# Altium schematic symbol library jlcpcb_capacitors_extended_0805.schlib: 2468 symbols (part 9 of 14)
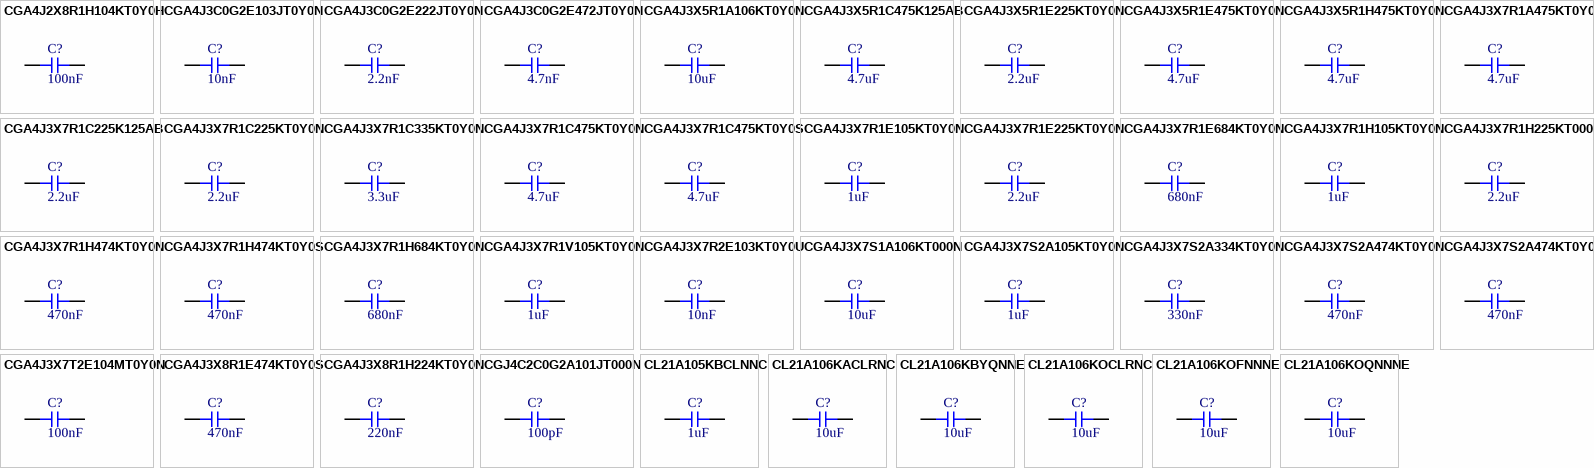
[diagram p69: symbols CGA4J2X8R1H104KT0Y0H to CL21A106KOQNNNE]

## CGA4J3X8R1H224KT0Y0N
designator C?  Capacitance: 220nF  (hidden comment: *)
Capacitor, Ceramic (MLCC), 220nF, ±10%, 50V, X8R, ±10%, SMD 0805; Manufacturer: TDK; Manufacturer Part Number: CGA4J3X8R1H224KT0Y0N
footprint CAP-0805 (0805 (2012M) Capacitor)
pins: 1, 2

## CGJ4C2C0G2A101JT000N
designator C?  Capacitance: 100pF  (hidden comment: *)
Capacitor, Ceramic (MLCC), 100pF, ±5%, 100V, C0G, ±5%, SMD 0805; Manufacturer: TDK; Manufacturer Part Number: CGJ4C2C0G2A101JT000N
footprint CAP-0805 (0805 (2012M) Capacitor)
pins: 1, 2

## CL21A105KBCLNNC
designator C?  Capacitance: 1uF  (hidden comment: *)
Capacitor, Ceramic (MLCC), 1uF, ±10%, 50V, X5R, ±10%, SMD 0805; Manufacturer: Samsung Electro-Mechanics; Manufacturer Part Number: CL21A105KBCLNNC
footprint CAP-0805 (0805 (2012M) Capacitor)
pins: 1, 2

## CL21A106KACLRNC
designator C?  Capacitance: 10uF  (hidden comment: *)
Capacitor, Ceramic (MLCC), 10uF, ±10%, 25V, X5R, ±10%, SMD 0805; Manufacturer: Samsung Electro-Mechanics; Manufacturer Part Number: CL21A106KACLRNC
footprint CAP-0805 (0805 (2012M) Capacitor)
pins: 1, 2

## CL21A106KBYQNNE
designator C?  Capacitance: 10uF  (hidden comment: *)
Capacitor, Ceramic (MLCC), 10uF, ±10%, 50V, X5R, ±10%, SMD 0805; Manufacturer: Samsung Electro-Mechanics; Manufacturer Part Number: CL21A106KBYQNNE
footprint CAP-0805 (0805 (2012M) Capacitor)
pins: 1, 2

## CL21A106KOCLRNC
designator C?  Capacitance: 10uF  (hidden comment: *)
Capacitor, Ceramic (MLCC), 10uF, ±10%, 16V, X5R, ±10%, SMD 0805; Manufacturer: Samsung Electro-Mechanics; Manufacturer Part Number: CL21A106KOCLRNC
footprint CAP-0805 (0805 (2012M) Capacitor)
pins: 1, 2

## CL21A106KOFNNNE
designator C?  Capacitance: 10uF  (hidden comment: *)
Capacitor, Ceramic (MLCC), 10uF, ±10%, 16V, X5R, ±10%, SMD 0805; Manufacturer: Samsung Electro-Mechanics; Manufacturer Part Number: CL21A106KOFNNNE
footprint CAP-0805 (0805 (2012M) Capacitor)
pins: 1, 2

## CL21A106KOQNNNE
designator C?  Capacitance: 10uF  (hidden comment: *)
Capacitor, Ceramic (MLCC), 10uF, ±10%, 16V, X5R, ±10%, SMD 0805; Manufacturer: Samsung Electro-Mechanics; Manufacturer Part Number: CL21A106KOQNNNE
footprint CAP-0805 (0805 (2012M) Capacitor)
pins: 1, 2

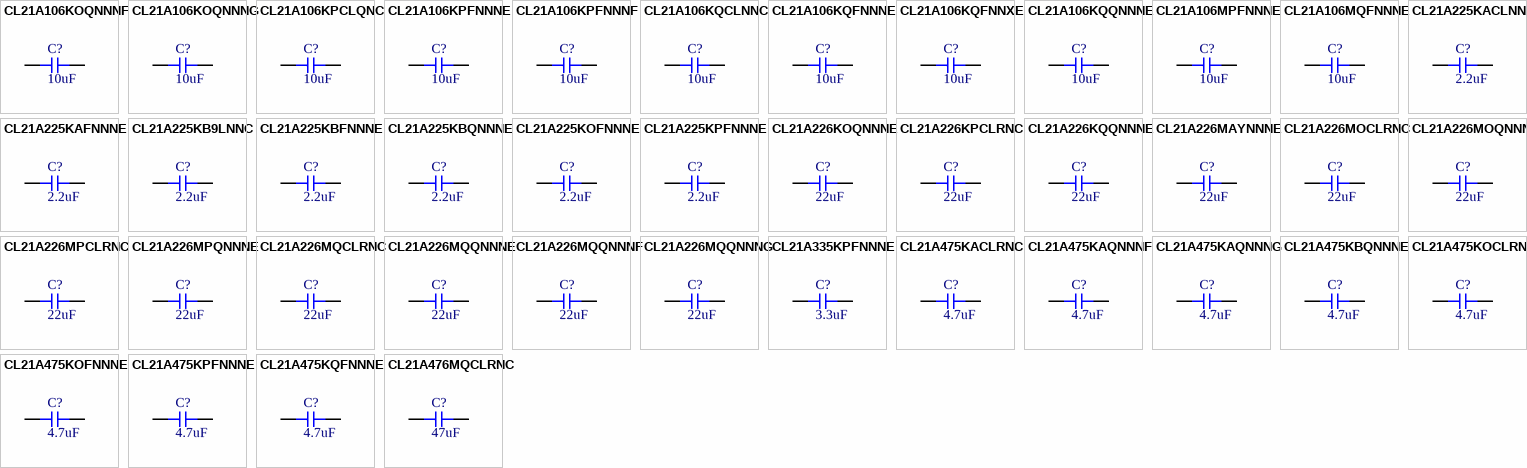
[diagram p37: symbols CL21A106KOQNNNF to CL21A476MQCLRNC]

## CL21A106KOQNNNF
designator C?  Capacitance: 10uF  (hidden comment: *)
Capacitor, Ceramic (MLCC), 10uF, ±10%, 16V, X5R, ±10%, SMD 0805; Manufacturer: Samsung Electro-Mechanics; Manufacturer Part Number: CL21A106KOQNNNF
footprint CAP-0805 (0805 (2012M) Capacitor)
pins: 1, 2

## CL21A106KOQNNNG
designator C?  Capacitance: 10uF  (hidden comment: *)
Capacitor, Ceramic (MLCC), 10uF, ±10%, 16V, X5R, ±10%, SMD 0805; Manufacturer: Samsung Electro-Mechanics; Manufacturer Part Number: CL21A106KOQNNNG
footprint CAP-0805 (0805 (2012M) Capacitor)
pins: 1, 2

## CL21A106KPCLQNC
designator C?  Capacitance: 10uF  (hidden comment: *)
Capacitor, Ceramic (MLCC), 10uF, ±10%, 10V, ±10%, SMD 0805; Manufacturer: Samsung Electro-Mechanics; Manufacturer Part Number: CL21A106KPCLQNC
footprint CAP-0805 (0805 (2012M) Capacitor)
pins: 1, 2

## CL21A106KPFNNNE
designator C?  Capacitance: 10uF  (hidden comment: *)
Capacitor, Ceramic (MLCC), 10uF, ±10%, 10V, X5R, ±10%, SMD 0805; Manufacturer: Samsung Electro-Mechanics; Manufacturer Part Number: CL21A106KPFNNNE
footprint CAP-0805 (0805 (2012M) Capacitor)
pins: 1, 2

## CL21A106KPFNNNF
designator C?  Capacitance: 10uF  (hidden comment: *)
Capacitor, Ceramic (MLCC), 10uF, ±10%, 10V, X5R, ±10%, SMD 0805; Manufacturer: Samsung Electro-Mechanics; Manufacturer Part Number: CL21A106KPFNNNF
footprint CAP-0805 (0805 (2012M) Capacitor)
pins: 1, 2

## CL21A106KQCLNNC
designator C?  Capacitance: 10uF  (hidden comment: *)
Capacitor, Ceramic (MLCC), 10uF, ±10%, 6.3V, X5R, ±10%, SMD 0805; Manufacturer: Samsung Electro-Mechanics; Manufacturer Part Number: CL21A106KQCLNNC
footprint CAP-0805 (0805 (2012M) Capacitor)
pins: 1, 2

## CL21A106KQFNNNE
designator C?  Capacitance: 10uF  (hidden comment: *)
Capacitor, Ceramic (MLCC), 10uF, ±10%, 6.3V, X5R, ±10%, SMD 0805; Manufacturer: Samsung Electro-Mechanics; Manufacturer Part Number: CL21A106KQFNNNE
footprint CAP-0805 (0805 (2012M) Capacitor)
pins: 1, 2

## CL21A106KQFNNXE
designator C?  Capacitance: 10uF  (hidden comment: *)
Capacitor, Ceramic (MLCC), 10uF, ±10%, 6.3V, X5R, ±10%, SMD 0805; Manufacturer: Samsung Electro-Mechanics; Manufacturer Part Number: CL21A106KQFNNXE
footprint CAP-0805 (0805 (2012M) Capacitor)
pins: 1, 2

## CL21A106KQQNNNE
designator C?  Capacitance: 10uF  (hidden comment: *)
Capacitor, Ceramic (MLCC), 10uF, ±10%, 6.3V, X5R, ±10%, SMD 0805; Manufacturer: Samsung Electro-Mechanics; Manufacturer Part Number: CL21A106KQQNNNE
footprint CAP-0805 (0805 (2012M) Capacitor)
pins: 1, 2

## CL21A106MPFNNNE
designator C?  Capacitance: 10uF  (hidden comment: *)
Capacitor, Ceramic (MLCC), 10uF, ±20%, 10V, X5R, ±20%, SMD 0805; Manufacturer: Samsung Electro-Mechanics; Manufacturer Part Number: CL21A106MPFNNNE
footprint CAP-0805 (0805 (2012M) Capacitor)
pins: 1, 2

## CL21A106MQFNNNE
designator C?  Capacitance: 10uF  (hidden comment: *)
Capacitor, Ceramic (MLCC), 10uF, ±20%, 6.3V, X5R, ±20%, SMD 0805; Manufacturer: Samsung Electro-Mechanics; Manufacturer Part Number: CL21A106MQFNNNE
footprint CAP-0805 (0805 (2012M) Capacitor)
pins: 1, 2

## CL21A225KACLNNC
designator C?  Capacitance: 2.2uF  (hidden comment: *)
Capacitor, Ceramic (MLCC), 2.2uF, ±10%, 25V, X5R, ±10%, SMD 0805; Manufacturer: Samsung Electro-Mechanics; Manufacturer Part Number: CL21A225KACLNNC
footprint CAP-0805 (0805 (2012M) Capacitor)
pins: 1, 2

## CL21A225KAFNNNE
designator C?  Capacitance: 2.2uF  (hidden comment: *)
Capacitor, Ceramic (MLCC), 2.2uF, ±10%, 25V, X5R, ±10%, SMD 0805; Manufacturer: Samsung Electro-Mechanics; Manufacturer Part Number: CL21A225KAFNNNE
footprint CAP-0805 (0805 (2012M) Capacitor)
pins: 1, 2

## CL21A225KB9LNNC
designator C?  Capacitance: 2.2uF  (hidden comment: *)
Capacitor, Ceramic (MLCC), 2.2uF, ±10%, 50V, X5R, ±10%, SMD 0805; Manufacturer: Samsung Electro-Mechanics; Manufacturer Part Number: CL21A225KB9LNNC
footprint CAP-0805 (0805 (2012M) Capacitor)
pins: 1, 2

## CL21A225KBFNNNE
designator C?  Capacitance: 2.2uF  (hidden comment: *)
Capacitor, Ceramic (MLCC), 2.2uF, ±10%, 50V, X5R, ±10%, SMD 0805; Manufacturer: Samsung Electro-Mechanics; Manufacturer Part Number: CL21A225KBFNNNE
footprint CAP-0805 (0805 (2012M) Capacitor)
pins: 1, 2

## CL21A225KBQNNNE
designator C?  Capacitance: 2.2uF  (hidden comment: *)
Capacitor, Ceramic (MLCC), 2.2uF, ±10%, 50V, X5R, ±10%, SMD 0805; Manufacturer: Samsung Electro-Mechanics; Manufacturer Part Number: CL21A225KBQNNNE
footprint CAP-0805 (0805 (2012M) Capacitor)
pins: 1, 2

## CL21A225KOFNNNE
designator C?  Capacitance: 2.2uF  (hidden comment: *)
Capacitor, Ceramic (MLCC), 2.2uF, ±10%, 16V, X5R, ±10%, SMD 0805; Manufacturer: Samsung Electro-Mechanics; Manufacturer Part Number: CL21A225KOFNNNE
footprint CAP-0805 (0805 (2012M) Capacitor)
pins: 1, 2

## CL21A225KPFNNNE
designator C?  Capacitance: 2.2uF  (hidden comment: *)
Capacitor, Ceramic (MLCC), 2.2uF, ±10%, 10V, X5R, ±10%, SMD 0805; Manufacturer: Samsung Electro-Mechanics; Manufacturer Part Number: CL21A225KPFNNNE
footprint CAP-0805 (0805 (2012M) Capacitor)
pins: 1, 2

## CL21A226KOQNNNE
designator C?  Capacitance: 22uF  (hidden comment: *)
Capacitor, Ceramic (MLCC), 22uF, ±10%, 16V, X5R, ±10%, SMD 0805; Manufacturer: Samsung Electro-Mechanics; Manufacturer Part Number: CL21A226KOQNNNE
footprint CAP-0805 (0805 (2012M) Capacitor)
pins: 1, 2

## CL21A226KPCLRNC
designator C?  Capacitance: 22uF  (hidden comment: *)
Capacitor, Ceramic (MLCC), 22uF, ±10%, 10V, X5R, ±10%, SMD 0805; Manufacturer: Samsung Electro-Mechanics; Manufacturer Part Number: CL21A226KPCLRNC
footprint CAP-0805 (0805 (2012M) Capacitor)
pins: 1, 2

## CL21A226KQQNNNE
designator C?  Capacitance: 22uF  (hidden comment: *)
Capacitor, Ceramic (MLCC), 22uF, ±10%, 6.3V, X5R, ±10%, SMD 0805; Manufacturer: Samsung Electro-Mechanics; Manufacturer Part Number: CL21A226KQQNNNE
footprint CAP-0805 (0805 (2012M) Capacitor)
pins: 1, 2

## CL21A226MAYNNNE
designator C?  Capacitance: 22uF  (hidden comment: *)
Capacitor, Ceramic (MLCC), 22uF, ±20%, 25V, X5R, ±20%, SMD 0805; Manufacturer: Samsung Electro-Mechanics; Manufacturer Part Number: CL21A226MAYNNNE
footprint CAP-0805 (0805 (2012M) Capacitor)
pins: 1, 2

## CL21A226MOCLRNC
designator C?  Capacitance: 22uF  (hidden comment: *)
Capacitor, Ceramic (MLCC), 22uF, ±20%, 16V, X5R, ±20%, SMD 0805; Manufacturer: Samsung Electro-Mechanics; Manufacturer Part Number: CL21A226MOCLRNC
footprint CAP-0805 (0805 (2012M) Capacitor)
pins: 1, 2

## CL21A226MOQNNNE
designator C?  Capacitance: 22uF  (hidden comment: *)
Capacitor, Ceramic (MLCC), 22uF, ±20%, 16V, X5R, ±20%, SMD 0805; Manufacturer: Samsung Electro-Mechanics; Manufacturer Part Number: CL21A226MOQNNNE
footprint CAP-0805 (0805 (2012M) Capacitor)
pins: 1, 2

## CL21A226MPCLRNC
designator C?  Capacitance: 22uF  (hidden comment: *)
Capacitor, Ceramic (MLCC), 22uF, ±20%, 10V, X5R, ±20%, SMD 0805; Manufacturer: Samsung Electro-Mechanics; Manufacturer Part Number: CL21A226MPCLRNC
footprint CAP-0805 (0805 (2012M) Capacitor)
pins: 1, 2

## CL21A226MPQNNNE
designator C?  Capacitance: 22uF  (hidden comment: *)
Capacitor, Ceramic (MLCC), 22uF, ±20%, 10V, X5R, ±20%, SMD 0805; Manufacturer: Samsung Electro-Mechanics; Manufacturer Part Number: CL21A226MPQNNNE
footprint CAP-0805 (0805 (2012M) Capacitor)
pins: 1, 2

## CL21A226MQCLRNC
designator C?  Capacitance: 22uF  (hidden comment: *)
Capacitor, Ceramic (MLCC), 22uF, ±20%, 6.3V, X5R, ±20%, SMD 0805; Manufacturer: Samsung Electro-Mechanics; Manufacturer Part Number: CL21A226MQCLRNC
footprint CAP-0805 (0805 (2012M) Capacitor)
pins: 1, 2

## CL21A226MQQNNNE
designator C?  Capacitance: 22uF  (hidden comment: *)
Capacitor, Ceramic (MLCC), 22uF, ±20%, 6.3V, X5R, ±20%, SMD 0805; Manufacturer: Samsung Electro-Mechanics; Manufacturer Part Number: CL21A226MQQNNNE
footprint CAP-0805 (0805 (2012M) Capacitor)
pins: 1, 2

## CL21A226MQQNNNF
designator C?  Capacitance: 22uF  (hidden comment: *)
Capacitor, Ceramic (MLCC), 22uF, ±20%, 6.3V, X5R, ±20%, SMD 0805; Manufacturer: Samsung Electro-Mechanics; Manufacturer Part Number: CL21A226MQQNNNF
footprint CAP-0805 (0805 (2012M) Capacitor)
pins: 1, 2

## CL21A226MQQNNNG
designator C?  Capacitance: 22uF  (hidden comment: *)
Capacitor, Ceramic (MLCC), 22uF, ±20%, 6.3V, X5R, ±20%, SMD 0805; Manufacturer: Samsung Electro-Mechanics; Manufacturer Part Number: CL21A226MQQNNNG
footprint CAP-0805 (0805 (2012M) Capacitor)
pins: 1, 2

## CL21A335KPFNNNE
designator C?  Capacitance: 3.3uF  (hidden comment: *)
Capacitor, Ceramic (MLCC), 3.3uF, ±10%, 10V, X5R, ±10%, SMD 0805; Manufacturer: Samsung Electro-Mechanics; Manufacturer Part Number: CL21A335KPFNNNE
footprint CAP-0805 (0805 (2012M) Capacitor)
pins: 1, 2

## CL21A475KACLRNC
designator C?  Capacitance: 4.7uF  (hidden comment: *)
Capacitor, Ceramic (MLCC), 4.7uF, ±10%, 25V, X5R, ±10%, SMD 0805; Manufacturer: Samsung Electro-Mechanics; Manufacturer Part Number: CL21A475KACLRNC
footprint CAP-0805 (0805 (2012M) Capacitor)
pins: 1, 2

## CL21A475KAQNNNF
designator C?  Capacitance: 4.7uF  (hidden comment: *)
Capacitor, Ceramic (MLCC), 4.7uF, ±10%, 25V, X5R, ±10%, SMD 0805; Manufacturer: Samsung Electro-Mechanics; Manufacturer Part Number: CL21A475KAQNNNF
footprint CAP-0805 (0805 (2012M) Capacitor)
pins: 1, 2

## CL21A475KAQNNNG
designator C?  Capacitance: 4.7uF  (hidden comment: *)
Capacitor, Ceramic (MLCC), 4.7uF, ±10%, 25V, X5R, ±10%, SMD 0805; Manufacturer: Samsung Electro-Mechanics; Manufacturer Part Number: CL21A475KAQNNNG
footprint CAP-0805 (0805 (2012M) Capacitor)
pins: 1, 2

## CL21A475KBQNNNE
designator C?  Capacitance: 4.7uF  (hidden comment: *)
Capacitor, Ceramic (MLCC), 4.7uF, ±10%, 50V, X5R, ±10%, SMD 0805; Manufacturer: Samsung Electro-Mechanics; Manufacturer Part Number: CL21A475KBQNNNE
footprint CAP-0805 (0805 (2012M) Capacitor)
pins: 1, 2

## CL21A475KOCLRNC
designator C?  Capacitance: 4.7uF  (hidden comment: *)
Capacitor, Ceramic (MLCC), 4.7uF, ±10%, 16V, X5R, ±10%, SMD 0805; Manufacturer: Samsung Electro-Mechanics; Manufacturer Part Number: CL21A475KOCLRNC
footprint CAP-0805 (0805 (2012M) Capacitor)
pins: 1, 2

## CL21A475KOFNNNE
designator C?  Capacitance: 4.7uF  (hidden comment: *)
Capacitor, Ceramic (MLCC), 4.7uF, ±10%, 16V, X5R, ±10%, SMD 0805; Manufacturer: Samsung Electro-Mechanics; Manufacturer Part Number: CL21A475KOFNNNE
footprint CAP-0805 (0805 (2012M) Capacitor)
pins: 1, 2

## CL21A475KPFNNNE
designator C?  Capacitance: 4.7uF  (hidden comment: *)
Capacitor, Ceramic (MLCC), 4.7uF, ±10%, 10V, X5R, ±10%, SMD 0805; Manufacturer: Samsung Electro-Mechanics; Manufacturer Part Number: CL21A475KPFNNNE
footprint CAP-0805 (0805 (2012M) Capacitor)
pins: 1, 2

## CL21A475KQFNNNE
designator C?  Capacitance: 4.7uF  (hidden comment: *)
Capacitor, Ceramic (MLCC), 4.7uF, ±10%, 6.3V, X5R, ±10%, SMD 0805; Manufacturer: Samsung Electro-Mechanics; Manufacturer Part Number: CL21A475KQFNNNE
footprint CAP-0805 (0805 (2012M) Capacitor)
pins: 1, 2

## CL21A476MQCLRNC
designator C?  Capacitance: 47uF  (hidden comment: *)
Capacitor, Ceramic (MLCC), 47uF, ±20%, 6.3V, X5R, ±20%, SMD 0805; Manufacturer: Samsung Electro-Mechanics; Manufacturer Part Number: CL21A476MQCLRNC
footprint CAP-0805 (0805 (2012M) Capacitor)
pins: 1, 2

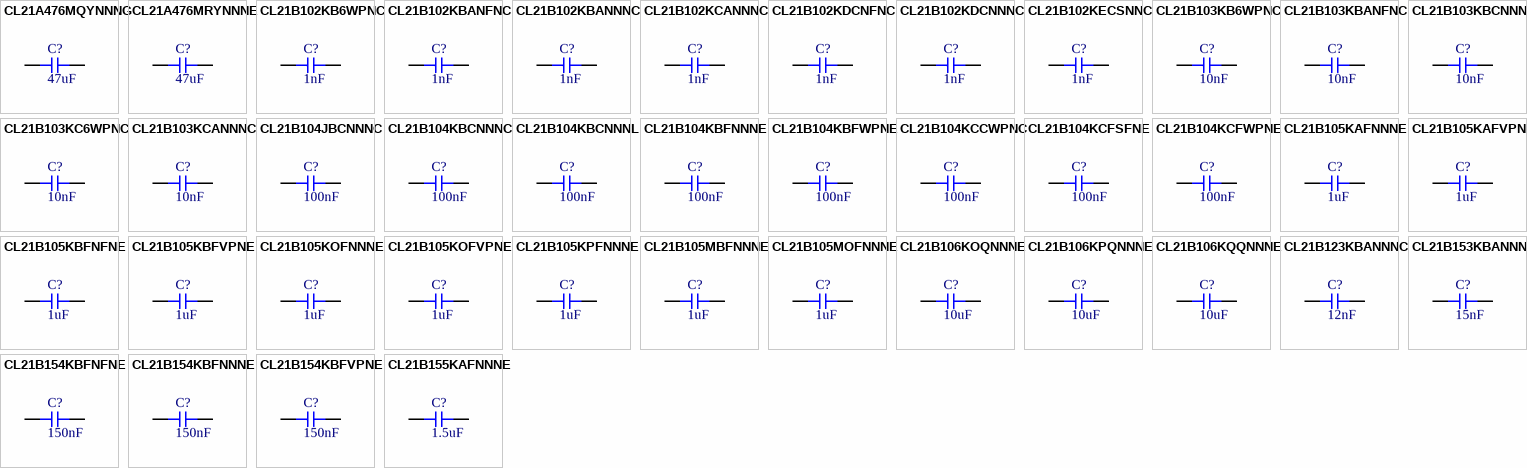
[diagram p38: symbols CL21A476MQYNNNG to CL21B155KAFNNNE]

## CL21A476MQYNNNG
designator C?  Capacitance: 47uF  (hidden comment: *)
Capacitor, Ceramic (MLCC), 47uF, ±20%, 6.3V, ±20%, SMD 0805; Manufacturer: Samsung Electro-Mechanics; Manufacturer Part Number: CL21A476MQYNNNG
footprint CAP-0805 (0805 (2012M) Capacitor)
pins: 1, 2

## CL21A476MRYNNNE
designator C?  Capacitance: 47uF  (hidden comment: *)
Capacitor, Ceramic (MLCC), 47uF, ±20%, 4V, X5R, ±20%, SMD 0805; Manufacturer: Samsung Electro-Mechanics; Manufacturer Part Number: CL21A476MRYNNNE
footprint CAP-0805 (0805 (2012M) Capacitor)
pins: 1, 2

## CL21B102KB6WPNC
designator C?  Capacitance: 1nF  (hidden comment: *)
Capacitor, Ceramic (MLCC), 1nF, ±10%, 50V, X7R, ±10%, SMD 0805; Manufacturer: Samsung Electro-Mechanics; Manufacturer Part Number: CL21B102KB6WPNC
footprint CAP-0805 (0805 (2012M) Capacitor)
pins: 1, 2

## CL21B102KBANFNC
designator C?  Capacitance: 1nF  (hidden comment: *)
Capacitor, Ceramic (MLCC), 1nF, ±10%, 50V, X7R, ±10%, SMD 0805; Manufacturer: Samsung Electro-Mechanics; Manufacturer Part Number: CL21B102KBANFNC
footprint CAP-0805 (0805 (2012M) Capacitor)
pins: 1, 2

## CL21B102KBANNNC
designator C?  Capacitance: 1nF  (hidden comment: *)
Capacitor, Ceramic (MLCC), 1nF, ±10%, 50V, X7R, ±10%, SMD 0805; Manufacturer: Samsung Electro-Mechanics; Manufacturer Part Number: CL21B102KBANNNC
footprint CAP-0805 (0805 (2012M) Capacitor)
pins: 1, 2

## CL21B102KCANNNC
designator C?  Capacitance: 1nF  (hidden comment: *)
Capacitor, Ceramic (MLCC), 1nF, ±10%, 100V, X7R, ±10%, SMD 0805; Manufacturer: Samsung Electro-Mechanics; Manufacturer Part Number: CL21B102KCANNNC
footprint CAP-0805 (0805 (2012M) Capacitor)
pins: 1, 2

## CL21B102KDCNFNC
designator C?  Capacitance: 1nF  (hidden comment: *)
Capacitor, Ceramic (MLCC), 1nF, ±10%, 200V, X7R, ±10%, SMD 0805; Manufacturer: Samsung Electro-Mechanics; Manufacturer Part Number: CL21B102KDCNFNC
footprint CAP-0805 (0805 (2012M) Capacitor)
pins: 1, 2

## CL21B102KDCNNNC
designator C?  Capacitance: 1nF  (hidden comment: *)
Capacitor, Ceramic (MLCC), 1nF, ±10%, 200V, X7R, ±10%, SMD 0805; Manufacturer: Samsung Electro-Mechanics; Manufacturer Part Number: CL21B102KDCNNNC
footprint CAP-0805 (0805 (2012M) Capacitor)
pins: 1, 2

## CL21B102KECSNNC
designator C?  Capacitance: 1nF  (hidden comment: *)
Capacitor, Ceramic (MLCC), 1nF, ±10%, 250V, X7R, ±10%, SMD 0805; Manufacturer: Samsung Electro-Mechanics; Manufacturer Part Number: CL21B102KECSNNC
footprint CAP-0805 (0805 (2012M) Capacitor)
pins: 1, 2

## CL21B103KB6WPNC
designator C?  Capacitance: 10nF  (hidden comment: *)
Capacitor, Ceramic (MLCC), 10nF, ±10%, 50V, X7R, ±10%, SMD 0805; Manufacturer: Samsung Electro-Mechanics; Manufacturer Part Number: CL21B103KB6WPNC
footprint CAP-0805 (0805 (2012M) Capacitor)
pins: 1, 2

## CL21B103KBANFNC
designator C?  Capacitance: 10nF  (hidden comment: *)
Capacitor, Ceramic (MLCC), 10nF, ±10%, 50V, X7R, ±10%, SMD 0805; Manufacturer: Samsung Electro-Mechanics; Manufacturer Part Number: CL21B103KBANFNC
footprint CAP-0805 (0805 (2012M) Capacitor)
pins: 1, 2

## CL21B103KBCNNNC
designator C?  Capacitance: 10nF  (hidden comment: *)
Capacitor, Ceramic (MLCC), 10nF, ±10%, 50V, X7R, ±10%, SMD 0805; Manufacturer: Samsung Electro-Mechanics; Manufacturer Part Number: CL21B103KBCNNNC
footprint CAP-0805 (0805 (2012M) Capacitor)
pins: 1, 2

## CL21B103KC6WPNC
designator C?  Capacitance: 10nF  (hidden comment: *)
Capacitor, Ceramic (MLCC), 10nF, ±10%, 100V, X7R, ±10%, SMD 0805; Manufacturer: Samsung Electro-Mechanics; Manufacturer Part Number: CL21B103KC6WPNC
footprint CAP-0805 (0805 (2012M) Capacitor)
pins: 1, 2

## CL21B103KCANNNC
designator C?  Capacitance: 10nF  (hidden comment: *)
Capacitor, Ceramic (MLCC), 10nF, ±10%, 100V, X7R, ±10%, SMD 0805; Manufacturer: Samsung Electro-Mechanics; Manufacturer Part Number: CL21B103KCANNNC
footprint CAP-0805 (0805 (2012M) Capacitor)
pins: 1, 2

## CL21B104JBCNNNC
designator C?  Capacitance: 100nF  (hidden comment: *)
Capacitor, Ceramic (MLCC), 100nF, ±5%, 50V, X7R, ±5%, SMD 0805; Manufacturer: Samsung Electro-Mechanics; Manufacturer Part Number: CL21B104JBCNNNC
footprint CAP-0805 (0805 (2012M) Capacitor)
pins: 1, 2

## CL21B104KBCNNNC
designator C?  Capacitance: 100nF  (hidden comment: *)
Capacitor, Ceramic (MLCC), 100nF, ±10%, 50V, X7R, ±10%, SMD 0805; Manufacturer: Samsung Electro-Mechanics; Manufacturer Part Number: CL21B104KBCNNNC
footprint CAP-0805 (0805 (2012M) Capacitor)
pins: 1, 2

## CL21B104KBCNNNL
designator C?  Capacitance: 100nF  (hidden comment: *)
Capacitor, Ceramic (MLCC), 100nF, ±10%, 50V, ±10%, SMD 0805; Manufacturer: Samsung Electro-Mechanics; Manufacturer Part Number: CL21B104KBCNNNL
footprint CAP-0805 (0805 (2012M) Capacitor)
pins: 1, 2

## CL21B104KBFNNNE
designator C?  Capacitance: 100nF  (hidden comment: *)
Capacitor, Ceramic (MLCC), 100nF, ±10%, 50V, X7R, ±10%, SMD 0805; Manufacturer: Samsung Electro-Mechanics; Manufacturer Part Number: CL21B104KBFNNNE
footprint CAP-0805 (0805 (2012M) Capacitor)
pins: 1, 2

## CL21B104KBFWPNE
designator C?  Capacitance: 100nF  (hidden comment: *)
Capacitor, Ceramic (MLCC), 100nF, ±10%, 50V, X7R, ±10%, SMD 0805; Manufacturer: Samsung Electro-Mechanics; Manufacturer Part Number: CL21B104KBFWPNE
footprint CAP-0805 (0805 (2012M) Capacitor)
pins: 1, 2

## CL21B104KCCWPNC
designator C?  Capacitance: 100nF  (hidden comment: *)
Capacitor, Ceramic (MLCC), 100nF, ±10%, 100V, X7R, ±10%, SMD 0805; Manufacturer: Samsung Electro-Mechanics; Manufacturer Part Number: CL21B104KCCWPNC
footprint CAP-0805 (0805 (2012M) Capacitor)
pins: 1, 2

## CL21B104KCFSFNE
designator C?  Capacitance: 100nF  (hidden comment: *)
Capacitor, Ceramic (MLCC), 100nF, ±10%, 100V, ±10%, SMD 0805; Manufacturer: Samsung Electro-Mechanics; Manufacturer Part Number: CL21B104KCFSFNE
footprint CAP-0805 (0805 (2012M) Capacitor)
pins: 1, 2

## CL21B104KCFWPNE
designator C?  Capacitance: 100nF  (hidden comment: *)
Capacitor, Ceramic (MLCC), 100nF, ±10%, 100V, X7R, ±10%, SMD 0805; Manufacturer: Samsung Electro-Mechanics; Manufacturer Part Number: CL21B104KCFWPNE
footprint CAP-0805 (0805 (2012M) Capacitor)
pins: 1, 2

## CL21B105KAFNNNE
designator C?  Capacitance: 1uF  (hidden comment: *)
Capacitor, Ceramic (MLCC), 1uF, ±10%, 25V, X7R, ±10%, SMD 0805; Manufacturer: Samsung Electro-Mechanics; Manufacturer Part Number: CL21B105KAFNNNE
footprint CAP-0805 (0805 (2012M) Capacitor)
pins: 1, 2

## CL21B105KAFVPNE
designator C?  Capacitance: 1uF  (hidden comment: *)
Capacitor, Ceramic (MLCC), 1uF, ±10%, 25V, X7R, ±10%, SMD 0805; Manufacturer: Samsung Electro-Mechanics; Manufacturer Part Number: CL21B105KAFVPNE
footprint CAP-0805 (0805 (2012M) Capacitor)
pins: 1, 2

## CL21B105KBFNFNE
designator C?  Capacitance: 1uF  (hidden comment: *)
Capacitor, Ceramic (MLCC), 1uF, ±10%, 50V, X7R, ±10%, SMD 0805; Manufacturer: Samsung Electro-Mechanics; Manufacturer Part Number: CL21B105KBFNFNE
footprint CAP-0805 (0805 (2012M) Capacitor)
pins: 1, 2

## CL21B105KBFVPNE
designator C?  Capacitance: 1uF  (hidden comment: *)
Capacitor, Ceramic (MLCC), 1uF, ±10%, 50V, X7R, ±10%, SMD 0805; Manufacturer: Samsung Electro-Mechanics; Manufacturer Part Number: CL21B105KBFVPNE
footprint CAP-0805 (0805 (2012M) Capacitor)
pins: 1, 2

## CL21B105KOFNNNE
designator C?  Capacitance: 1uF  (hidden comment: *)
Capacitor, Ceramic (MLCC), 1uF, ±10%, 16V, X7R, ±10%, SMD 0805; Manufacturer: Samsung Electro-Mechanics; Manufacturer Part Number: CL21B105KOFNNNE
footprint CAP-0805 (0805 (2012M) Capacitor)
pins: 1, 2

## CL21B105KOFVPNE
designator C?  Capacitance: 1uF  (hidden comment: *)
Capacitor, Ceramic (MLCC), 1uF, ±10%, 16V, X7R, ±10%, SMD 0805; Manufacturer: Samsung Electro-Mechanics; Manufacturer Part Number: CL21B105KOFVPNE
footprint CAP-0805 (0805 (2012M) Capacitor)
pins: 1, 2

## CL21B105KPFNNNE
designator C?  Capacitance: 1uF  (hidden comment: *)
Capacitor, Ceramic (MLCC), 1uF, ±10%, 10V, X7R, ±10%, SMD 0805; Manufacturer: Samsung Electro-Mechanics; Manufacturer Part Number: CL21B105KPFNNNE
footprint CAP-0805 (0805 (2012M) Capacitor)
pins: 1, 2

## CL21B105MBFNNNE
designator C?  Capacitance: 1uF  (hidden comment: *)
Capacitor, Ceramic (MLCC), 1uF, ±20%, 50V, ±20%, SMD 0805; Manufacturer: Samsung Electro-Mechanics; Manufacturer Part Number: CL21B105MBFNNNE
footprint CAP-0805 (0805 (2012M) Capacitor)
pins: 1, 2

## CL21B105MOFNNNE
designator C?  Capacitance: 1uF  (hidden comment: *)
Capacitor, Ceramic (MLCC), 1uF, ±20%, 16V, X7R, ±20%, SMD 0805; Manufacturer: Samsung Electro-Mechanics; Manufacturer Part Number: CL21B105MOFNNNE
footprint CAP-0805 (0805 (2012M) Capacitor)
pins: 1, 2

## CL21B106KOQNNNE
designator C?  Capacitance: 10uF  (hidden comment: *)
Capacitor, Ceramic (MLCC), 10uF, ±10%, 16V, X7R, ±10%, SMD 0805; Manufacturer: Samsung Electro-Mechanics; Manufacturer Part Number: CL21B106KOQNNNE
footprint CAP-0805 (0805 (2012M) Capacitor)
pins: 1, 2

## CL21B106KPQNNNE
designator C?  Capacitance: 10uF  (hidden comment: *)
Capacitor, Ceramic (MLCC), 10uF, ±10%, 10V, X7R, ±10%, SMD 0805; Manufacturer: Samsung Electro-Mechanics; Manufacturer Part Number: CL21B106KPQNNNE
footprint CAP-0805 (0805 (2012M) Capacitor)
pins: 1, 2

## CL21B106KQQNNNE
designator C?  Capacitance: 10uF  (hidden comment: *)
Capacitor, Ceramic (MLCC), 10uF, ±10%, 6.3V, X7R, ±10%, SMD 0805; Manufacturer: Samsung Electro-Mechanics; Manufacturer Part Number: CL21B106KQQNNNE
footprint CAP-0805 (0805 (2012M) Capacitor)
pins: 1, 2

## CL21B123KBANNNC
designator C?  Capacitance: 12nF  (hidden comment: *)
Capacitor, Ceramic (MLCC), 12nF, ±10%, 50V, X7R, ±10%, SMD 0805; Manufacturer: Samsung Electro-Mechanics; Manufacturer Part Number: CL21B123KBANNNC
footprint CAP-0805 (0805 (2012M) Capacitor)
pins: 1, 2

## CL21B153KBANNNC
designator C?  Capacitance: 15nF  (hidden comment: *)
Capacitor, Ceramic (MLCC), 15nF, ±10%, 50V, X7R, ±10%, SMD 0805; Manufacturer: Samsung Electro-Mechanics; Manufacturer Part Number: CL21B153KBANNNC
footprint CAP-0805 (0805 (2012M) Capacitor)
pins: 1, 2

## CL21B154KBFNFNE
designator C?  Capacitance: 150nF  (hidden comment: *)
Capacitor, Ceramic (MLCC), 150nF, ±10%, 50V, X7R, ±10%, SMD 0805; Manufacturer: Samsung Electro-Mechanics; Manufacturer Part Number: CL21B154KBFNFNE
footprint CAP-0805 (0805 (2012M) Capacitor)
pins: 1, 2

## CL21B154KBFNNNE
designator C?  Capacitance: 150nF  (hidden comment: *)
Capacitor, Ceramic (MLCC), 150nF, ±10%, 50V, X7R, ±10%, SMD 0805; Manufacturer: Samsung Electro-Mechanics; Manufacturer Part Number: CL21B154KBFNNNE
footprint CAP-0805 (0805 (2012M) Capacitor)
pins: 1, 2

## CL21B154KBFVPNE
designator C?  Capacitance: 150nF  (hidden comment: *)
Capacitor, Ceramic (MLCC), 150nF, ±10%, 50V, X7R, ±10%, SMD 0805; Manufacturer: Samsung Electro-Mechanics; Manufacturer Part Number: CL21B154KBFVPNE
footprint CAP-0805 (0805 (2012M) Capacitor)
pins: 1, 2

## CL21B155KAFNNNE
designator C?  Capacitance: 1.5uF  (hidden comment: *)
Capacitor, Ceramic (MLCC), 1.5uF, ±10%, 25V, X7R, ±10%, SMD 0805; Manufacturer: Samsung Electro-Mechanics; Manufacturer Part Number: CL21B155KAFNNNE
footprint CAP-0805 (0805 (2012M) Capacitor)
pins: 1, 2

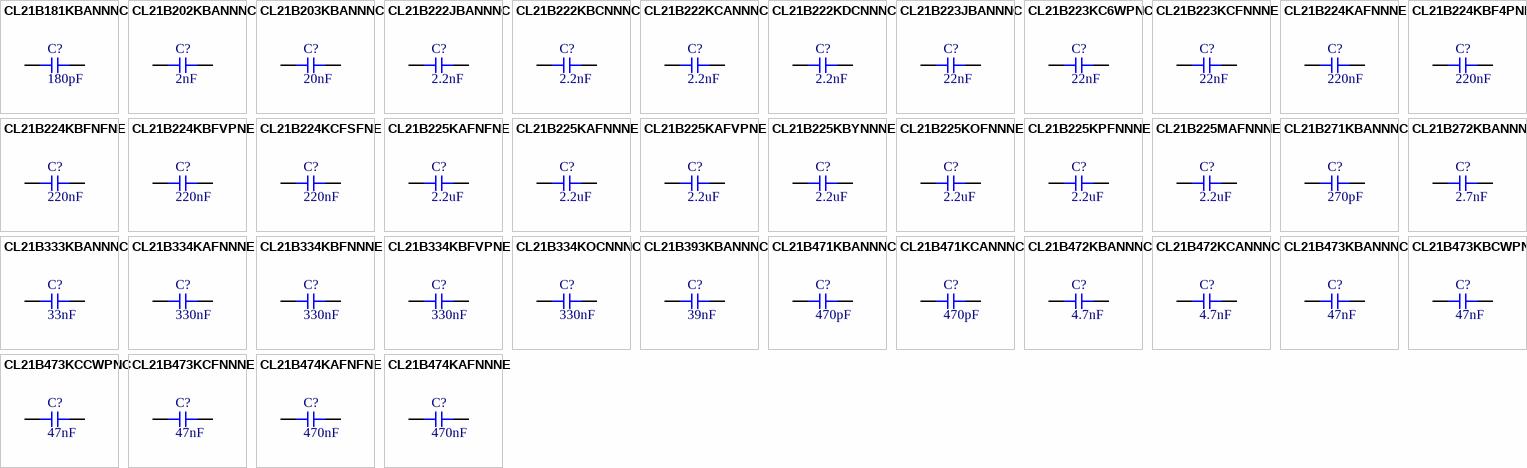
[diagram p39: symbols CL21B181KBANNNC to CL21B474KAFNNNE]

## CL21B181KBANNNC
designator C?  Capacitance: 180pF  (hidden comment: *)
Capacitor, Ceramic (MLCC), 180pF, ±10%, 50V, X7R, ±10%, SMD 0805; Manufacturer: Samsung Electro-Mechanics; Manufacturer Part Number: CL21B181KBANNNC
footprint CAP-0805 (0805 (2012M) Capacitor)
pins: 1, 2

## CL21B202KBANNNC
designator C?  Capacitance: 2nF  (hidden comment: *)
Capacitor, Ceramic (MLCC), 2nF, ±10%, 50V, X7R, ±10%, SMD 0805; Manufacturer: Samsung Electro-Mechanics; Manufacturer Part Number: CL21B202KBANNNC
footprint CAP-0805 (0805 (2012M) Capacitor)
pins: 1, 2

## CL21B203KBANNNC
designator C?  Capacitance: 20nF  (hidden comment: *)
Capacitor, Ceramic (MLCC), 20nF, ±10%, 50V, X7R, ±10%, SMD 0805; Manufacturer: Samsung Electro-Mechanics; Manufacturer Part Number: CL21B203KBANNNC
footprint CAP-0805 (0805 (2012M) Capacitor)
pins: 1, 2

## CL21B222JBANNNC
designator C?  Capacitance: 2.2nF  (hidden comment: *)
Capacitor, Ceramic (MLCC), 2.2nF, ±5%, 50V, X7R, ±5%, SMD 0805; Manufacturer: Samsung Electro-Mechanics; Manufacturer Part Number: CL21B222JBANNNC
footprint CAP-0805 (0805 (2012M) Capacitor)
pins: 1, 2

## CL21B222KBCNNNC
designator C?  Capacitance: 2.2nF  (hidden comment: *)
Capacitor, Ceramic (MLCC), 2.2nF, ±10%, 50V, X7R, ±10%, SMD 0805; Manufacturer: Samsung Electro-Mechanics; Manufacturer Part Number: CL21B222KBCNNNC
footprint CAP-0805 (0805 (2012M) Capacitor)
pins: 1, 2

## CL21B222KCANNNC
designator C?  Capacitance: 2.2nF  (hidden comment: *)
Capacitor, Ceramic (MLCC), 2.2nF, ±10%, 100V, X7R, ±10%, SMD 0805; Manufacturer: Samsung Electro-Mechanics; Manufacturer Part Number: CL21B222KCANNNC
footprint CAP-0805 (0805 (2012M) Capacitor)
pins: 1, 2

## CL21B222KDCNNNC
designator C?  Capacitance: 2.2nF  (hidden comment: *)
Capacitor, Ceramic (MLCC), 2.2nF, ±10%, 200V, X7R, ±10%, SMD 0805; Manufacturer: Samsung Electro-Mechanics; Manufacturer Part Number: CL21B222KDCNNNC
footprint CAP-0805 (0805 (2012M) Capacitor)
pins: 1, 2

## CL21B223JBANNNC
designator C?  Capacitance: 22nF  (hidden comment: *)
Capacitor, Ceramic (MLCC), 22nF, ±5%, 50V, X7R, ±5%, SMD 0805; Manufacturer: Samsung Electro-Mechanics; Manufacturer Part Number: CL21B223JBANNNC
footprint CAP-0805 (0805 (2012M) Capacitor)
pins: 1, 2

## CL21B223KC6WPNC
designator C?  Capacitance: 22nF  (hidden comment: *)
Capacitor, Ceramic (MLCC), 22nF, ±10%, 100V, X7R, ±10%, SMD 0805; Manufacturer: Samsung Electro-Mechanics; Manufacturer Part Number: CL21B223KC6WPNC
footprint CAP-0805 (0805 (2012M) Capacitor)
pins: 1, 2

## CL21B223KCFNNNE
designator C?  Capacitance: 22nF  (hidden comment: *)
Capacitor, Ceramic (MLCC), 22nF, ±10%, 100V, X7R, ±10%, SMD 0805; Manufacturer: Samsung Electro-Mechanics; Manufacturer Part Number: CL21B223KCFNNNE
footprint CAP-0805 (0805 (2012M) Capacitor)
pins: 1, 2

## CL21B224KAFNNNE
designator C?  Capacitance: 220nF  (hidden comment: *)
Capacitor, Ceramic (MLCC), 220nF, ±10%, 25V, X7R, ±10%, SMD 0805; Manufacturer: Samsung Electro-Mechanics; Manufacturer Part Number: CL21B224KAFNNNE
footprint CAP-0805 (0805 (2012M) Capacitor)
pins: 1, 2

## CL21B224KBF4PNE
designator C?  Capacitance: 220nF  (hidden comment: *)
Capacitor, Ceramic (MLCC), 220nF, ±10%, 50V, X7R, ±10%, SMD 0805; Manufacturer: Samsung Electro-Mechanics; Manufacturer Part Number: CL21B224KBF4PNE
footprint CAP-0805 (0805 (2012M) Capacitor)
pins: 1, 2

## CL21B224KBFNFNE
designator C?  Capacitance: 220nF  (hidden comment: *)
Capacitor, Ceramic (MLCC), 220nF, ±10%, 50V, X7R, ±10%, SMD 0805; Manufacturer: Samsung Electro-Mechanics; Manufacturer Part Number: CL21B224KBFNFNE
footprint CAP-0805 (0805 (2012M) Capacitor)
pins: 1, 2

## CL21B224KBFVPNE
designator C?  Capacitance: 220nF  (hidden comment: *)
Capacitor, Ceramic (MLCC), 220nF, ±10%, 50V, X7R, ±10%, SMD 0805; Manufacturer: Samsung Electro-Mechanics; Manufacturer Part Number: CL21B224KBFVPNE
footprint CAP-0805 (0805 (2012M) Capacitor)
pins: 1, 2

## CL21B224KCFSFNE
designator C?  Capacitance: 220nF  (hidden comment: *)
Capacitor, Ceramic (MLCC), 220nF, ±10%, 100V, X7R, ±10%, SMD 0805; Manufacturer: Samsung Electro-Mechanics; Manufacturer Part Number: CL21B224KCFSFNE
footprint CAP-0805 (0805 (2012M) Capacitor)
pins: 1, 2

## CL21B225KAFNFNE
designator C?  Capacitance: 2.2uF  (hidden comment: *)
Capacitor, Ceramic (MLCC), 2.2uF, ±10%, 25V, X7R, ±10%, SMD 0805; Manufacturer: Samsung Electro-Mechanics; Manufacturer Part Number: CL21B225KAFNFNE
footprint CAP-0805 (0805 (2012M) Capacitor)
pins: 1, 2

## CL21B225KAFNNNE
designator C?  Capacitance: 2.2uF  (hidden comment: *)
Capacitor, Ceramic (MLCC), 2.2uF, ±10%, 25V, X7R, ±10%, SMD 0805; Manufacturer: Samsung Electro-Mechanics; Manufacturer Part Number: CL21B225KAFNNNE
footprint CAP-0805 (0805 (2012M) Capacitor)
pins: 1, 2

## CL21B225KAFVPNE
designator C?  Capacitance: 2.2uF  (hidden comment: *)
Capacitor, Ceramic (MLCC), 2.2uF, ±10%, 25V, X7R, ±10%, SMD 0805; Manufacturer: Samsung Electro-Mechanics; Manufacturer Part Number: CL21B225KAFVPNE
footprint CAP-0805 (0805 (2012M) Capacitor)
pins: 1, 2

## CL21B225KBYNNNE
designator C?  Capacitance: 2.2uF  (hidden comment: *)
Capacitor, Ceramic (MLCC), 2.2uF, ±10%, 50V, ±10%, SMD 0805; Manufacturer: Samsung Electro-Mechanics; Manufacturer Part Number: CL21B225KBYNNNE
footprint CAP-0805 (0805 (2012M) Capacitor)
pins: 1, 2

## CL21B225KOFNNNE
designator C?  Capacitance: 2.2uF  (hidden comment: *)
Capacitor, Ceramic (MLCC), 2.2uF, ±10%, 16V, X7R, ±10%, SMD 0805; Manufacturer: Samsung Electro-Mechanics; Manufacturer Part Number: CL21B225KOFNNNE
footprint CAP-0805 (0805 (2012M) Capacitor)
pins: 1, 2

## CL21B225KPFNNNE
designator C?  Capacitance: 2.2uF  (hidden comment: *)
Capacitor, Ceramic (MLCC), 2.2uF, ±10%, 10V, X7R, ±10%, SMD 0805; Manufacturer: Samsung Electro-Mechanics; Manufacturer Part Number: CL21B225KPFNNNE
footprint CAP-0805 (0805 (2012M) Capacitor)
pins: 1, 2

## CL21B225MAFNNNE
designator C?  Capacitance: 2.2uF  (hidden comment: *)
Capacitor, Ceramic (MLCC), 2.2uF, ±20%, 25V, X7R, ±20%, SMD 0805; Manufacturer: Samsung Electro-Mechanics; Manufacturer Part Number: CL21B225MAFNNNE
footprint CAP-0805 (0805 (2012M) Capacitor)
pins: 1, 2

## CL21B271KBANNNC
designator C?  Capacitance: 270pF  (hidden comment: *)
Capacitor, Ceramic (MLCC), 270pF, ±10%, 50V, X7R, ±10%, SMD 0805; Manufacturer: Samsung Electro-Mechanics; Manufacturer Part Number: CL21B271KBANNNC
footprint CAP-0805 (0805 (2012M) Capacitor)
pins: 1, 2

## CL21B272KBANNNC
designator C?  Capacitance: 2.7nF  (hidden comment: *)
Capacitor, Ceramic (MLCC), 2.7nF, ±10%, 50V, X7R, ±10%, SMD 0805; Manufacturer: Samsung Electro-Mechanics; Manufacturer Part Number: CL21B272KBANNNC
footprint CAP-0805 (0805 (2012M) Capacitor)
pins: 1, 2

## CL21B333KBANNNC
designator C?  Capacitance: 33nF  (hidden comment: *)
Capacitor, Ceramic (MLCC), 33nF, ±10%, 50V, X7R, ±10%, SMD 0805; Manufacturer: Samsung Electro-Mechanics; Manufacturer Part Number: CL21B333KBANNNC
footprint CAP-0805 (0805 (2012M) Capacitor)
pins: 1, 2

## CL21B334KAFNNNE
designator C?  Capacitance: 330nF  (hidden comment: *)
Capacitor, Ceramic (MLCC), 330nF, ±10%, 25V, X7R, ±10%, SMD 0805; Manufacturer: Samsung Electro-Mechanics; Manufacturer Part Number: CL21B334KAFNNNE
footprint CAP-0805 (0805 (2012M) Capacitor)
pins: 1, 2

## CL21B334KBFNNNE
designator C?  Capacitance: 330nF  (hidden comment: *)
Capacitor, Ceramic (MLCC), 330nF, ±10%, 50V, X7R, ±10%, SMD 0805; Manufacturer: Samsung Electro-Mechanics; Manufacturer Part Number: CL21B334KBFNNNE
footprint CAP-0805 (0805 (2012M) Capacitor)
pins: 1, 2

## CL21B334KBFVPNE
designator C?  Capacitance: 330nF  (hidden comment: *)
Capacitor, Ceramic (MLCC), 330nF, ±10%, 50V, X7R, ±10%, SMD 0805; Manufacturer: Samsung Electro-Mechanics; Manufacturer Part Number: CL21B334KBFVPNE
footprint CAP-0805 (0805 (2012M) Capacitor)
pins: 1, 2

## CL21B334KOCNNNC
designator C?  Capacitance: 330nF  (hidden comment: *)
Capacitor, Ceramic (MLCC), 330nF, ±10%, 16V, X7R, ±10%, SMD 0805; Manufacturer: Samsung Electro-Mechanics; Manufacturer Part Number: CL21B334KOCNNNC
footprint CAP-0805 (0805 (2012M) Capacitor)
pins: 1, 2

## CL21B393KBANNNC
designator C?  Capacitance: 39nF  (hidden comment: *)
Capacitor, Ceramic (MLCC), 39nF, ±10%, 50V, X7R, ±10%, SMD 0805; Manufacturer: Samsung Electro-Mechanics; Manufacturer Part Number: CL21B393KBANNNC
footprint CAP-0805 (0805 (2012M) Capacitor)
pins: 1, 2

## CL21B471KBANNNC
designator C?  Capacitance: 470pF  (hidden comment: *)
Capacitor, Ceramic (MLCC), 470pF, ±10%, 50V, X7R, ±10%, SMD 0805; Manufacturer: Samsung Electro-Mechanics; Manufacturer Part Number: CL21B471KBANNNC
footprint CAP-0805 (0805 (2012M) Capacitor)
pins: 1, 2

## CL21B471KCANNNC
designator C?  Capacitance: 470pF  (hidden comment: *)
Capacitor, Ceramic (MLCC), 470pF, ±10%, 100V, X7R, ±10%, SMD 0805; Manufacturer: Samsung Electro-Mechanics; Manufacturer Part Number: CL21B471KCANNNC
footprint CAP-0805 (0805 (2012M) Capacitor)
pins: 1, 2

## CL21B472KBANNNC
designator C?  Capacitance: 4.7nF  (hidden comment: *)
Capacitor, Ceramic (MLCC), 4.7nF, ±10%, 50V, X7R, ±10%, SMD 0805; Manufacturer: Samsung Electro-Mechanics; Manufacturer Part Number: CL21B472KBANNNC
footprint CAP-0805 (0805 (2012M) Capacitor)
pins: 1, 2

## CL21B472KCANNNC
designator C?  Capacitance: 4.7nF  (hidden comment: *)
Capacitor, Ceramic (MLCC), 4.7nF, ±10%, 100V, X7R, ±10%, SMD 0805; Manufacturer: Samsung Electro-Mechanics; Manufacturer Part Number: CL21B472KCANNNC
footprint CAP-0805 (0805 (2012M) Capacitor)
pins: 1, 2

## CL21B473KBANNNC
designator C?  Capacitance: 47nF  (hidden comment: *)
Capacitor, Ceramic (MLCC), 47nF, ±10%, 50V, X7R, ±10%, SMD 0805; Manufacturer: Samsung Electro-Mechanics; Manufacturer Part Number: CL21B473KBANNNC
footprint CAP-0805 (0805 (2012M) Capacitor)
pins: 1, 2

## CL21B473KBCWPNC
designator C?  Capacitance: 47nF  (hidden comment: *)
Capacitor, Ceramic (MLCC), 47nF, ±10%, 50V, X7R, ±10%, SMD 0805; Manufacturer: Samsung Electro-Mechanics; Manufacturer Part Number: CL21B473KBCWPNC
footprint CAP-0805 (0805 (2012M) Capacitor)
pins: 1, 2

## CL21B473KCCWPNC
designator C?  Capacitance: 47nF  (hidden comment: *)
Capacitor, Ceramic (MLCC), 47nF, ±10%, 100V, X7R, ±10%, SMD 0805; Manufacturer: Samsung Electro-Mechanics; Manufacturer Part Number: CL21B473KCCWPNC
footprint CAP-0805 (0805 (2012M) Capacitor)
pins: 1, 2

## CL21B473KCFNNNE
designator C?  Capacitance: 47nF  (hidden comment: *)
Capacitor, Ceramic (MLCC), 47nF, ±10%, 100V, X7R, ±10%, SMD 0805; Manufacturer: Samsung Electro-Mechanics; Manufacturer Part Number: CL21B473KCFNNNE
footprint CAP-0805 (0805 (2012M) Capacitor)
pins: 1, 2

## CL21B474KAFNFNE
designator C?  Capacitance: 470nF  (hidden comment: *)
Capacitor, Ceramic (MLCC), 470nF, ±10%, 25V, X7R, ±10%, SMD 0805; Manufacturer: Samsung Electro-Mechanics; Manufacturer Part Number: CL21B474KAFNFNE
footprint CAP-0805 (0805 (2012M) Capacitor)
pins: 1, 2

## CL21B474KAFNNNE
designator C?  Capacitance: 470nF  (hidden comment: *)
Capacitor, Ceramic (MLCC), 470nF, ±10%, 25V, X7R, ±10%, SMD 0805; Manufacturer: Samsung Electro-Mechanics; Manufacturer Part Number: CL21B474KAFNNNE
footprint CAP-0805 (0805 (2012M) Capacitor)
pins: 1, 2

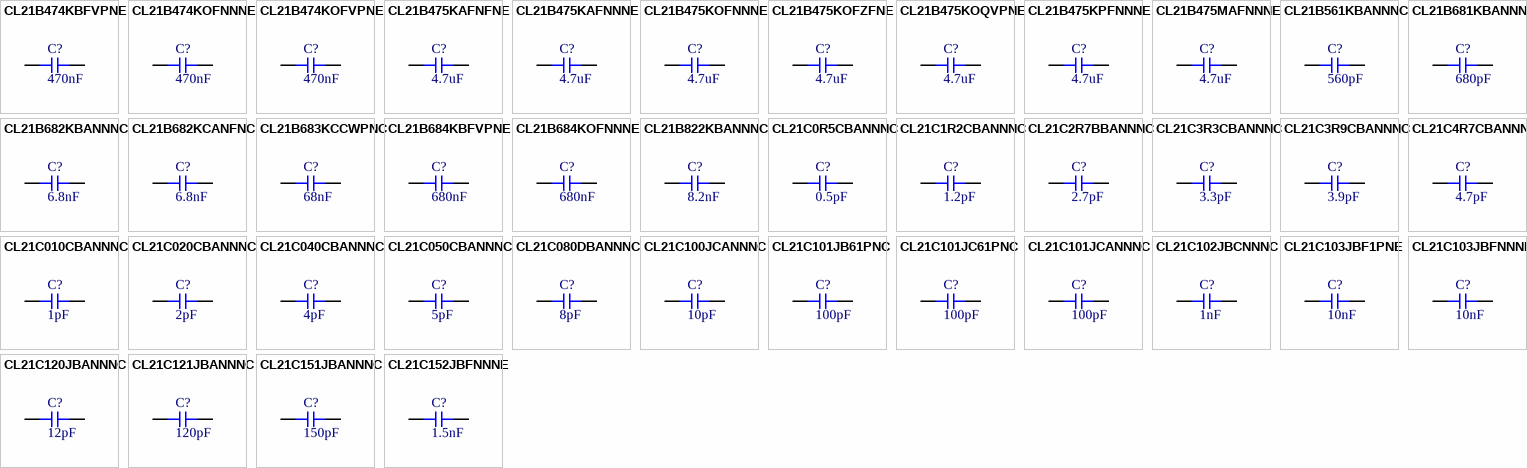
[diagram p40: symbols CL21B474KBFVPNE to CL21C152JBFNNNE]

## CL21B474KBFVPNE
designator C?  Capacitance: 470nF  (hidden comment: *)
Capacitor, Ceramic (MLCC), 470nF, ±10%, 50V, X7R, ±10%, SMD 0805; Manufacturer: Samsung Electro-Mechanics; Manufacturer Part Number: CL21B474KBFVPNE
footprint CAP-0805 (0805 (2012M) Capacitor)
pins: 1, 2

## CL21B474KOFNNNE
designator C?  Capacitance: 470nF  (hidden comment: *)
Capacitor, Ceramic (MLCC), 470nF, ±10%, 16V, X7R, ±10%, SMD 0805; Manufacturer: Samsung Electro-Mechanics; Manufacturer Part Number: CL21B474KOFNNNE
footprint CAP-0805 (0805 (2012M) Capacitor)
pins: 1, 2

## CL21B474KOFVPNE
designator C?  Capacitance: 470nF  (hidden comment: *)
Capacitor, Ceramic (MLCC), 470nF, ±10%, 16V, X7R, ±10%, SMD 0805; Manufacturer: Samsung Electro-Mechanics; Manufacturer Part Number: CL21B474KOFVPNE
footprint CAP-0805 (0805 (2012M) Capacitor)
pins: 1, 2

## CL21B475KAFNFNE
designator C?  Capacitance: 4.7uF  (hidden comment: *)
Capacitor, Ceramic (MLCC), 4.7uF, ±10%, 25V, X7R, ±10%, SMD 0805; Manufacturer: Samsung Electro-Mechanics; Manufacturer Part Number: CL21B475KAFNFNE
footprint CAP-0805 (0805 (2012M) Capacitor)
pins: 1, 2

## CL21B475KAFNNNE
designator C?  Capacitance: 4.7uF  (hidden comment: *)
Capacitor, Ceramic (MLCC), 4.7uF, ±10%, 25V, X7R, ±10%, SMD 0805; Manufacturer: Samsung Electro-Mechanics; Manufacturer Part Number: CL21B475KAFNNNE
footprint CAP-0805 (0805 (2012M) Capacitor)
pins: 1, 2

## CL21B475KOFNNNE
designator C?  Capacitance: 4.7uF  (hidden comment: *)
Capacitor, Ceramic (MLCC), 4.7uF, ±10%, 16V, X7R, ±10%, SMD 0805; Manufacturer: Samsung Electro-Mechanics; Manufacturer Part Number: CL21B475KOFNNNE
footprint CAP-0805 (0805 (2012M) Capacitor)
pins: 1, 2

## CL21B475KOFZFNE
designator C?  Capacitance: 4.7uF  (hidden comment: *)
Capacitor, Ceramic (MLCC), 4.7uF, ±10%, 16V, X7R, ±10%, SMD 0805; Manufacturer: Samsung Electro-Mechanics; Manufacturer Part Number: CL21B475KOFZFNE
footprint CAP-0805 (0805 (2012M) Capacitor)
pins: 1, 2

## CL21B475KOQVPNE
designator C?  Capacitance: 4.7uF  (hidden comment: *)
Capacitor, Ceramic (MLCC), 4.7uF, ±10%, 16V, X7R, ±10%, SMD 0805; Manufacturer: Samsung Electro-Mechanics; Manufacturer Part Number: CL21B475KOQVPNE
footprint CAP-0805 (0805 (2012M) Capacitor)
pins: 1, 2

## CL21B475KPFNNNE
designator C?  Capacitance: 4.7uF  (hidden comment: *)
Capacitor, Ceramic (MLCC), 4.7uF, ±10%, 10V, X7R, ±10%, SMD 0805; Manufacturer: Samsung Electro-Mechanics; Manufacturer Part Number: CL21B475KPFNNNE
footprint CAP-0805 (0805 (2012M) Capacitor)
pins: 1, 2

## CL21B475MAFNNNE
designator C?  Capacitance: 4.7uF  (hidden comment: *)
Capacitor, Ceramic (MLCC), 4.7uF, ±20%, 25V, X7R, ±20%, SMD 0805; Manufacturer: Samsung Electro-Mechanics; Manufacturer Part Number: CL21B475MAFNNNE
footprint CAP-0805 (0805 (2012M) Capacitor)
pins: 1, 2

## CL21B561KBANNNC
designator C?  Capacitance: 560pF  (hidden comment: *)
Capacitor, Ceramic (MLCC), 560pF, ±10%, 50V, X7R, ±10%, SMD 0805; Manufacturer: Samsung Electro-Mechanics; Manufacturer Part Number: CL21B561KBANNNC
footprint CAP-0805 (0805 (2012M) Capacitor)
pins: 1, 2

## CL21B681KBANNNC
designator C?  Capacitance: 680pF  (hidden comment: *)
Capacitor, Ceramic (MLCC), 680pF, ±10%, 50V, X7R, ±10%, SMD 0805; Manufacturer: Samsung Electro-Mechanics; Manufacturer Part Number: CL21B681KBANNNC
footprint CAP-0805 (0805 (2012M) Capacitor)
pins: 1, 2

## CL21B682KBANNNC
designator C?  Capacitance: 6.8nF  (hidden comment: *)
Capacitor, Ceramic (MLCC), 6.8nF, ±10%, 50V, X7R, ±10%, SMD 0805; Manufacturer: Samsung Electro-Mechanics; Manufacturer Part Number: CL21B682KBANNNC
footprint CAP-0805 (0805 (2012M) Capacitor)
pins: 1, 2

## CL21B682KCANFNC
designator C?  Capacitance: 6.8nF  (hidden comment: *)
Capacitor, Ceramic (MLCC), 6.8nF, ±10%, 100V, X7R, ±10%, SMD 0805; Manufacturer: Samsung Electro-Mechanics; Manufacturer Part Number: CL21B682KCANFNC
footprint CAP-0805 (0805 (2012M) Capacitor)
pins: 1, 2

## CL21B683KCCWPNC
designator C?  Capacitance: 68nF  (hidden comment: *)
Capacitor, Ceramic (MLCC), 68nF, ±10%, 100V, X7R, ±10%, SMD 0805; Manufacturer: Samsung Electro-Mechanics; Manufacturer Part Number: CL21B683KCCWPNC
footprint CAP-0805 (0805 (2012M) Capacitor)
pins: 1, 2

## CL21B684KBFVPNE
designator C?  Capacitance: 680nF  (hidden comment: *)
Capacitor, Ceramic (MLCC), 680nF, ±10%, 50V, X7R, ±10%, SMD 0805; Manufacturer: Samsung Electro-Mechanics; Manufacturer Part Number: CL21B684KBFVPNE
footprint CAP-0805 (0805 (2012M) Capacitor)
pins: 1, 2

## CL21B684KOFNNNE
designator C?  Capacitance: 680nF  (hidden comment: *)
Capacitor, Ceramic (MLCC), 680nF, ±10%, 16V, X7R, ±10%, SMD 0805; Manufacturer: Samsung Electro-Mechanics; Manufacturer Part Number: CL21B684KOFNNNE
footprint CAP-0805 (0805 (2012M) Capacitor)
pins: 1, 2

## CL21B822KBANNNC
designator C?  Capacitance: 8.2nF  (hidden comment: *)
Capacitor, Ceramic (MLCC), 8.2nF, ±10%, 50V, X7R, ±10%, SMD 0805; Manufacturer: Samsung Electro-Mechanics; Manufacturer Part Number: CL21B822KBANNNC
footprint CAP-0805 (0805 (2012M) Capacitor)
pins: 1, 2

## CL21C0R5CBANNNC
designator C?  Capacitance: 0.5pF  (hidden comment: *)
Capacitor, Ceramic (MLCC), 0.5pF, ±0.25pF, 50V, C0G, ±0.25pF, SMD 0805; Manufacturer: Samsung Electro-Mechanics; Manufacturer Part Number: CL21C0R5CBANNNC
footprint CAP-0805 (0805 (2012M) Capacitor)
pins: 1, 2

## CL21C1R2CBANNNC
designator C?  Capacitance: 1.2pF  (hidden comment: *)
Capacitor, Ceramic (MLCC), 1.2pF, ±0.25pF, 50V, C0G, ±0.25pF, SMD 0805; Manufacturer: Samsung Electro-Mechanics; Manufacturer Part Number: CL21C1R2CBANNNC
footprint CAP-0805 (0805 (2012M) Capacitor)
pins: 1, 2

## CL21C2R7BBANNNC
designator C?  Capacitance: 2.7pF  (hidden comment: *)
Capacitor, Ceramic (MLCC), 2.7pF, ±0.1pF, 50V, C0G, ±0.1pF, SMD 0805; Manufacturer: Samsung Electro-Mechanics; Manufacturer Part Number: CL21C2R7BBANNNC
footprint CAP-0805 (0805 (2012M) Capacitor)
pins: 1, 2

## CL21C3R3CBANNNC
designator C?  Capacitance: 3.3pF  (hidden comment: *)
Capacitor, Ceramic (MLCC), 3.3pF, ±0.25pF, 50V, C0G, ±0.25pF, SMD 0805; Manufacturer: Samsung Electro-Mechanics; Manufacturer Part Number: CL21C3R3CBANNNC
footprint CAP-0805 (0805 (2012M) Capacitor)
pins: 1, 2

## CL21C3R9CBANNNC
designator C?  Capacitance: 3.9pF  (hidden comment: *)
Capacitor, Ceramic (MLCC), 3.9pF, ±0.25pF, 50V, C0G, ±0.25pF, SMD 0805; Manufacturer: Samsung Electro-Mechanics; Manufacturer Part Number: CL21C3R9CBANNNC
footprint CAP-0805 (0805 (2012M) Capacitor)
pins: 1, 2

## CL21C4R7CBANNNC
designator C?  Capacitance: 4.7pF  (hidden comment: *)
Capacitor, Ceramic (MLCC), 4.7pF, ±0.25pF, 50V, C0G, ±0.25pF, SMD 0805; Manufacturer: Samsung Electro-Mechanics; Manufacturer Part Number: CL21C4R7CBANNNC
footprint CAP-0805 (0805 (2012M) Capacitor)
pins: 1, 2

## CL21C010CBANNNC
designator C?  Capacitance: 1pF  (hidden comment: *)
Capacitor, Ceramic (MLCC), 1pF, ±0.25pF, 50V, C0G, ±0.25pF, SMD 0805; Manufacturer: Samsung Electro-Mechanics; Manufacturer Part Number: CL21C010CBANNNC
footprint CAP-0805 (0805 (2012M) Capacitor)
pins: 1, 2

## CL21C020CBANNNC
designator C?  Capacitance: 2pF  (hidden comment: *)
Capacitor, Ceramic (MLCC), 2pF, ±0.25pF, 50V, C0G, ±0.25pF, SMD 0805; Manufacturer: Samsung Electro-Mechanics; Manufacturer Part Number: CL21C020CBANNNC
footprint CAP-0805 (0805 (2012M) Capacitor)
pins: 1, 2

## CL21C040CBANNNC
designator C?  Capacitance: 4pF  (hidden comment: *)
Capacitor, Ceramic (MLCC), 4pF, ±0.25pF, 50V, C0G, ±0.25pF, SMD 0805; Manufacturer: Samsung Electro-Mechanics; Manufacturer Part Number: CL21C040CBANNNC
footprint CAP-0805 (0805 (2012M) Capacitor)
pins: 1, 2

## CL21C050CBANNNC
designator C?  Capacitance: 5pF  (hidden comment: *)
Capacitor, Ceramic (MLCC), 5pF, ±0.25pF, 50V, C0G, ±0.25pF, SMD 0805; Manufacturer: Samsung Electro-Mechanics; Manufacturer Part Number: CL21C050CBANNNC
footprint CAP-0805 (0805 (2012M) Capacitor)
pins: 1, 2

## CL21C080DBANNNC
designator C?  Capacitance: 8pF  (hidden comment: *)
Capacitor, Ceramic (MLCC), 8pF, ±0.5pF, 50V, C0G, ±0.5pF, SMD 0805; Manufacturer: Samsung Electro-Mechanics; Manufacturer Part Number: CL21C080DBANNNC
footprint CAP-0805 (0805 (2012M) Capacitor)
pins: 1, 2

## CL21C100JCANNNC
designator C?  Capacitance: 10pF  (hidden comment: *)
Capacitor, Ceramic (MLCC), 10pF, ±5%, 100V, C0G, ±5%, SMD 0805; Manufacturer: Samsung Electro-Mechanics; Manufacturer Part Number: CL21C100JCANNNC
footprint CAP-0805 (0805 (2012M) Capacitor)
pins: 1, 2

## CL21C101JB61PNC
designator C?  Capacitance: 100pF  (hidden comment: *)
Capacitor, Ceramic (MLCC), 100pF, ±5%, 50V, C0G, ±5%, SMD 0805; Manufacturer: Samsung Electro-Mechanics; Manufacturer Part Number: CL21C101JB61PNC
footprint CAP-0805 (0805 (2012M) Capacitor)
pins: 1, 2

## CL21C101JC61PNC
designator C?  Capacitance: 100pF  (hidden comment: *)
Capacitor, Ceramic (MLCC), 100pF, ±5%, 100V, C0G, ±5%, SMD 0805; Manufacturer: Samsung Electro-Mechanics; Manufacturer Part Number: CL21C101JC61PNC
footprint CAP-0805 (0805 (2012M) Capacitor)
pins: 1, 2

## CL21C101JCANNNC
designator C?  Capacitance: 100pF  (hidden comment: *)
Capacitor, Ceramic (MLCC), 100pF, ±5%, 100V, C0G, ±5%, SMD 0805; Manufacturer: Samsung Electro-Mechanics; Manufacturer Part Number: CL21C101JCANNNC
footprint CAP-0805 (0805 (2012M) Capacitor)
pins: 1, 2

## CL21C102JBCNNNC
designator C?  Capacitance: 1nF  (hidden comment: *)
Capacitor, Ceramic (MLCC), 1nF, ±5%, 50V, C0G, ±5%, SMD 0805; Manufacturer: Samsung Electro-Mechanics; Manufacturer Part Number: CL21C102JBCNNNC
footprint CAP-0805 (0805 (2012M) Capacitor)
pins: 1, 2

## CL21C103JBF1PNE
designator C?  Capacitance: 10nF  (hidden comment: *)
Capacitor, Ceramic (MLCC), 10nF, ±5%, 50V, C0G, ±5%, SMD 0805; Manufacturer: Samsung Electro-Mechanics; Manufacturer Part Number: CL21C103JBF1PNE
footprint CAP-0805 (0805 (2012M) Capacitor)
pins: 1, 2

## CL21C103JBFNNNE
designator C?  Capacitance: 10nF  (hidden comment: *)
Capacitor, Ceramic (MLCC), 10nF, ±5%, 50V, C0G, ±5%, SMD 0805; Manufacturer: Samsung Electro-Mechanics; Manufacturer Part Number: CL21C103JBFNNNE
footprint CAP-0805 (0805 (2012M) Capacitor)
pins: 1, 2

## CL21C120JBANNNC
designator C?  Capacitance: 12pF  (hidden comment: *)
Capacitor, Ceramic (MLCC), 12pF, ±5%, 50V, C0G, ±5%, SMD 0805; Manufacturer: Samsung Electro-Mechanics; Manufacturer Part Number: CL21C120JBANNNC
footprint CAP-0805 (0805 (2012M) Capacitor)
pins: 1, 2

## CL21C121JBANNNC
designator C?  Capacitance: 120pF  (hidden comment: *)
Capacitor, Ceramic (MLCC), 120pF, ±5%, 50V, C0G, ±5%, SMD 0805; Manufacturer: Samsung Electro-Mechanics; Manufacturer Part Number: CL21C121JBANNNC
footprint CAP-0805 (0805 (2012M) Capacitor)
pins: 1, 2

## CL21C151JBANNNC
designator C?  Capacitance: 150pF  (hidden comment: *)
Capacitor, Ceramic (MLCC), 150pF, ±5%, 50V, C0G, ±5%, SMD 0805; Manufacturer: Samsung Electro-Mechanics; Manufacturer Part Number: CL21C151JBANNNC
footprint CAP-0805 (0805 (2012M) Capacitor)
pins: 1, 2

## CL21C152JBFNNNE
designator C?  Capacitance: 1.5nF  (hidden comment: *)
Capacitor, Ceramic (MLCC), 1.5nF, ±5%, 50V, C0G, ±5%, SMD 0805; Manufacturer: Samsung Electro-Mechanics; Manufacturer Part Number: CL21C152JBFNNNE
footprint CAP-0805 (0805 (2012M) Capacitor)
pins: 1, 2

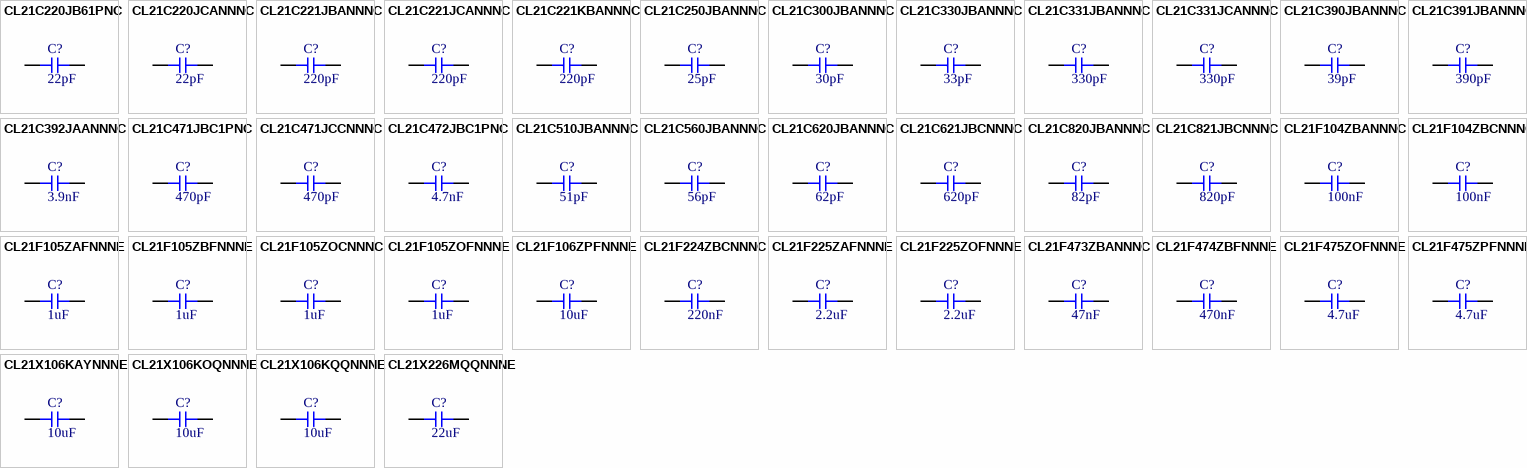
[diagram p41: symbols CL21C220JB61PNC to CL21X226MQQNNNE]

## CL21C220JB61PNC
designator C?  Capacitance: 22pF  (hidden comment: *)
Capacitor, Ceramic (MLCC), 22pF, ±5%, 50V, ±5%, SMD 0805; Manufacturer: Samsung Electro-Mechanics; Manufacturer Part Number: CL21C220JB61PNC
footprint CAP-0805 (0805 (2012M) Capacitor)
pins: 1, 2

## CL21C220JCANNNC
designator C?  Capacitance: 22pF  (hidden comment: *)
Capacitor, Ceramic (MLCC), 22pF, ±5%, 100V, C0G, ±5%, SMD 0805; Manufacturer: Samsung Electro-Mechanics; Manufacturer Part Number: CL21C220JCANNNC
footprint CAP-0805 (0805 (2012M) Capacitor)
pins: 1, 2

## CL21C221JBANNNC
designator C?  Capacitance: 220pF  (hidden comment: *)
Capacitor, Ceramic (MLCC), 220pF, ±5%, 50V, C0G, ±5%, SMD 0805; Manufacturer: Samsung Electro-Mechanics; Manufacturer Part Number: CL21C221JBANNNC
footprint CAP-0805 (0805 (2012M) Capacitor)
pins: 1, 2

## CL21C221JCANNNC
designator C?  Capacitance: 220pF  (hidden comment: *)
Capacitor, Ceramic (MLCC), 220pF, ±5%, 100V, C0G, ±5%, SMD 0805; Manufacturer: Samsung Electro-Mechanics; Manufacturer Part Number: CL21C221JCANNNC
footprint CAP-0805 (0805 (2012M) Capacitor)
pins: 1, 2

## CL21C221KBANNNC
designator C?  Capacitance: 220pF  (hidden comment: *)
Capacitor, Ceramic (MLCC), 220pF, ±10%, 50V, ±10%, SMD 0805; Manufacturer: Samsung Electro-Mechanics; Manufacturer Part Number: CL21C221KBANNNC
footprint CAP-0805 (0805 (2012M) Capacitor)
pins: 1, 2

## CL21C250JBANNNC
designator C?  Capacitance: 25pF  (hidden comment: *)
Capacitor, Ceramic (MLCC), 25pF, ±5%, 50V, C0G, ±5%, SMD 0805; Manufacturer: Samsung Electro-Mechanics; Manufacturer Part Number: CL21C250JBANNNC
footprint CAP-0805 (0805 (2012M) Capacitor)
pins: 1, 2

## CL21C300JBANNNC
designator C?  Capacitance: 30pF  (hidden comment: *)
Capacitor, Ceramic (MLCC), 30pF, ±5%, 50V, C0G, ±5%, SMD 0805; Manufacturer: Samsung Electro-Mechanics; Manufacturer Part Number: CL21C300JBANNNC
footprint CAP-0805 (0805 (2012M) Capacitor)
pins: 1, 2

## CL21C330JBANNNC
designator C?  Capacitance: 33pF  (hidden comment: *)
Capacitor, Ceramic (MLCC), 33pF, ±5%, 50V, C0G, ±5%, SMD 0805; Manufacturer: Samsung Electro-Mechanics; Manufacturer Part Number: CL21C330JBANNNC
footprint CAP-0805 (0805 (2012M) Capacitor)
pins: 1, 2

## CL21C331JBANNNC
designator C?  Capacitance: 330pF  (hidden comment: *)
Capacitor, Ceramic (MLCC), 330pF, ±5%, 50V, C0G, ±5%, SMD 0805; Manufacturer: Samsung Electro-Mechanics; Manufacturer Part Number: CL21C331JBANNNC
footprint CAP-0805 (0805 (2012M) Capacitor)
pins: 1, 2

## CL21C331JCANNNC
designator C?  Capacitance: 330pF  (hidden comment: *)
Capacitor, Ceramic (MLCC), 330pF, ±5%, 100V, C0G, ±5%, SMD 0805; Manufacturer: Samsung Electro-Mechanics; Manufacturer Part Number: CL21C331JCANNNC
footprint CAP-0805 (0805 (2012M) Capacitor)
pins: 1, 2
